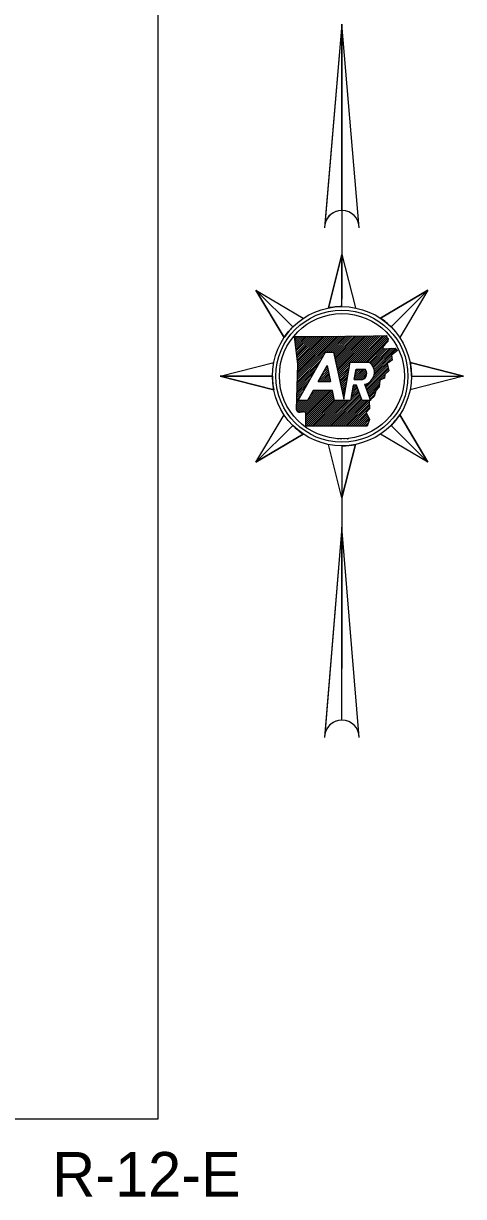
# Model space of a CAD drawing. Extents: x 171 to 3403, y 68 to 2102.
# Drawn here: x 2434 to 2632, y 198 to 725 of the extents above; entities that cross this region are included whole.
import ezdxf

# ---------------------------------------------------------------- set-up
doc = ezdxf.new("R2010")
doc.units = 0
for name, color, linetype in [('Default', 7, 'Continuous'), ('R_Draft', 7, 'Continuous'), ('R_No Plot', 7, 'Continuous')]:
    doc.layers.add(name, color=color, linetype=linetype)

msp = doc.modelspace()

# ---------------------------------------------------------------- linework, layer by layer
at = {"layer": 'R_Draft'}
for p, q in [((2576.92, 724.57), (2569.22, 634.49)), ((2576.92, 724.57), (2576.92, 601.2)), ((2576.92, 640.98), (2576.92, 724.57)), ((2569.33, 635.75), (2569.68, 636.1)), ((2569.37, 636.23), (2570.08, 636.94)), ((2576.92, 621.23), (2570.83, 597.19)), ((2576.92, 597.79), (2576.92, 621.23)), ((2538.25, 605.21), (2554.82, 588.64)), ((2554.82, 588.64), (2538.25, 605.21)), ((2538.25, 605.21), (2550.94, 583.91)), ((2615.59, 605.21), (2594.29, 592.52)), ((2599.01, 588.64), (2615.59, 605.21)), ((2599.01, 588.64), (2615.59, 605.21)), ((2555.62, 584.15), (2555.89, 584.43)), ((2555.71, 583.37), (2556.78, 584.43)), ((2555.81, 582.58), (2557.66, 584.43)), ((2555.91, 581.79), (2558.54, 584.43)), ((2556.01, 581.01), (2559.43, 584.43)), ((2556.11, 580.22), (2560.31, 584.43)), ((2556.2, 579.44), (2561.19, 584.42)), ((2556.3, 578.65), (2562.08, 584.42)), ((2556.4, 577.86), (2562.96, 584.42)), ((2556.5, 577.08), (2563.84, 584.42)), ((2556.6, 576.29), (2564.73, 584.42)), ((2556.69, 575.51), (2565.61, 584.42)), ((2556.79, 574.72), (2566.49, 584.42)), ((2556.89, 573.93), (2567.38, 584.42)), ((2556.92, 565.13), (2576.23, 584.44)), ((2556.95, 566.04), (2575.35, 584.44)), ((2556.98, 566.95), (2574.46, 584.43)), ((2556.99, 573.15), (2568.26, 584.42)), ((2557.01, 567.87), (2573.57, 584.43)), ((2557.04, 568.78), (2572.69, 584.43)), ((2557.07, 569.7), (2571.8, 584.43)), ((2557.08, 572.36), (2569.15, 584.42)), ((2557.1, 570.61), (2570.92, 584.43)), ((2557.13, 571.52), (2570.03, 584.43)), ((2570.04, 577.37), (2577.12, 584.44)), ((2570.93, 577.37), (2578, 584.44)), ((2571.81, 577.37), (2578.89, 584.45)), ((2572.7, 577.37), (2579.79, 584.46)), ((2573.25, 577.03), (2580.69, 584.48)), ((2573.4, 576.31), (2581.59, 584.49)), ((2573.56, 575.58), (2582.49, 584.51)), ((2573.71, 574.85), (2583.38, 584.52)), ((2573.87, 574.12), (2584.28, 584.53)), ((2574.03, 573.39), (2585.18, 584.55)), ((2574.18, 572.67), (2586.08, 584.56)), ((2574.34, 571.94), (2586.98, 584.58)), ((2574.49, 571.21), (2587.87, 584.59)), ((2574.65, 570.48), (2588.77, 584.6)), ((2574.8, 569.75), (2589.67, 584.62)), ((2574.96, 569.02), (2590.57, 584.63)), ((2575.12, 568.3), (2591.47, 584.65)), ((2575.27, 567.57), (2592.37, 584.67)), ((2581.41, 572.82), (2593.28, 584.69)), ((2582.3, 572.82), (2594.18, 584.71)), ((2583.18, 572.82), (2595.09, 584.73)), ((2584.06, 572.82), (2595.99, 584.75)), ((2584.95, 572.82), (2596.9, 584.77)), ((2585.83, 572.82), (2597.09, 584.09)), ((2586.72, 572.82), (2597.52, 583.63)), ((2587.6, 572.82), (2597.63, 582.86)), ((2588.48, 572.82), (2595.62, 579.96)), ((2556.89, 564.21), (2568.82, 576.14)), ((2557.18, 555.59), (2569.51, 577.37)), ((2569.51, 577.37), (2573.18, 577.37)), ((2589.29, 572.74), (2595.44, 578.9)), ((2589.77, 572.34), (2596.37, 578.95)), ((2590.2, 571.89), (2597.31, 579)), ((2590.58, 571.39), (2598.24, 579.04)), ((2590.91, 570.83), (2599.17, 579.09)), ((2591.18, 570.22), (2600.1, 579.14)), ((2591.32, 566.83), (2599.35, 574.85)), ((2591.38, 569.54), (2600.94, 579.1)), ((2591.5, 568.77), (2601.35, 578.62)), ((2591.51, 567.89), (2599.24, 575.63)), ((2600.96, 577.35), (2601.77, 578.15)), ((2556.8, 561.47), (2565.35, 570.02)), ((2556.83, 562.38), (2566.51, 572.06)), ((2556.86, 563.3), (2567.66, 574.1)), ((2566.25, 564.14), (2570.28, 571.26)), ((2567.35, 566.08), (2570.68, 569.41)), ((2568.5, 568.12), (2570.52, 570.14)), ((2569.66, 570.15), (2570.37, 570.87)), ((2575.43, 566.84), (2580.44, 571.86)), ((2575.58, 566.11), (2580.26, 570.79)), ((2575.74, 565.38), (2580.07, 569.72)), ((2580.61, 572.82), (2589.17, 572.82)), ((2582.48, 565.1), (2587.13, 569.75)), ((2582.66, 566.17), (2586.24, 569.75)), ((2582.84, 567.24), (2585.36, 569.75)), ((2583.03, 568.31), (2584.47, 569.75)), ((2583.22, 569.38), (2583.59, 569.75)), ((2583.28, 569.75), (2587.3, 569.75)), ((2583.36, 565.1), (2587.62, 569.36)), ((2587.67, 561.41), (2597.47, 571.21)), ((2587.91, 560.76), (2597.64, 570.49)), ((2588.15, 560.12), (2597.8, 569.77)), ((2588.39, 559.47), (2597.97, 569.05)), ((2590.55, 565.17), (2597.31, 571.93)), ((2598.36, 572.97), (2599.45, 574.07)), ((2631.6, 566.54), (2607.57, 572.62)), ((2522.23, 566.54), (2545.67, 566.54)), ((2545.67, 566.54), (2522.23, 566.54)), ((2522.23, 566.54), (2546.27, 560.45)), ((2556.71, 558.73), (2561.89, 563.91)), ((2556.74, 559.64), (2563.05, 565.95)), ((2556.77, 560.55), (2564.2, 567.99)), ((2566.25, 564.14), (2571.81, 564.14)), ((2566.29, 564.14), (2570.84, 568.68)), ((2567.18, 564.14), (2570.99, 567.95)), ((2568.06, 564.14), (2571.15, 567.22)), ((2568.95, 564.14), (2571.3, 566.5)), ((2569.83, 564.14), (2571.46, 565.77)), ((2570.71, 564.14), (2571.62, 565.04)), ((2571.6, 564.14), (2571.77, 564.31)), ((2575.9, 564.66), (2579.88, 568.64)), ((2576.05, 563.93), (2579.7, 567.57)), ((2576.21, 563.2), (2579.51, 566.5)), ((2576.36, 562.47), (2579.32, 565.43)), ((2576.52, 561.74), (2579.14, 564.36)), ((2582.47, 565.1), (2586.14, 565.1)), ((2584.24, 565.1), (2587.92, 568.77)), ((2585.13, 565.1), (2588.08, 568.05)), ((2586.01, 565.1), (2588.01, 567.1)), ((2588.63, 558.83), (2593.93, 564.13)), ((2594.95, 565.15), (2596.19, 566.39)), ((2608.17, 566.54), (2631.6, 566.54)), ((2608.17, 566.54), (2631.6, 566.54)), ((2556.65, 556.9), (2559.58, 559.84)), ((2556.68, 557.81), (2560.74, 561.87)), ((2556.81, 550.87), (2566.1, 560.16)), ((2557.33, 550.51), (2566.98, 560.16)), ((2557.97, 550.26), (2567.86, 560.16)), ((2559.02, 550.43), (2568.75, 560.16)), ((2559.91, 550.44), (2569.63, 560.16)), ((2560.61, 550.25), (2570.52, 560.16)), ((2560.64, 548.52), (2572.28, 560.16)), ((2560.64, 549.4), (2571.4, 560.16)), ((2560.64, 547.63), (2572.75, 559.74)), ((2560.64, 546.75), (2572.91, 559.01)), ((2564, 560.16), (2561.41, 555.59)), ((2562.41, 557.36), (2565.21, 560.16)), ((2563.57, 559.4), (2564.33, 560.16)), ((2572.66, 560.16), (2564, 560.16)), ((2569.49, 544.11), (2584.69, 559.31)), ((2570.37, 544.1), (2584.93, 558.66)), ((2576.67, 561.02), (2578.95, 563.29)), ((2576.83, 560.29), (2578.76, 562.22)), ((2576.99, 559.56), (2578.58, 561.15)), ((2577.14, 558.83), (2578.39, 560.08)), ((2577.3, 558.1), (2578.2, 559.01)), ((2580.97, 556.47), (2584.45, 559.95)), ((2581.15, 557.54), (2584.21, 560.6)), ((2581.34, 558.61), (2583.97, 561.24)), ((2581.53, 559.68), (2583.74, 561.89)), ((2581.71, 560.75), (2583.48, 562.52)), ((2581.9, 561.82), (2582.6, 562.52)), ((2583.5, 562.52), (2582.02, 562.52)), ((2586.06, 555.59), (2583.5, 562.52)), ((2587.13, 562.89), (2589.82, 555.59)), ((2587.2, 562.7), (2587.47, 562.97)), ((2587.44, 562.05), (2589.12, 563.74)), ((2588.87, 558.18), (2593.83, 563.15)), ((2589.11, 557.54), (2593.73, 562.16)), ((2589.34, 556.89), (2592.05, 559.6)), ((2556.48, 551.43), (2560.64, 555.59)), ((2556.49, 552.33), (2559.76, 555.59)), ((2556.52, 553.24), (2558.88, 555.59)), ((2556.55, 554.15), (2557.99, 555.59)), ((2556.58, 555.07), (2557.28, 555.76)), ((2556.62, 555.98), (2558.43, 557.8)), ((2561.41, 555.59), (2557.18, 555.59)), ((2560.65, 545.87), (2573.06, 558.29)), ((2560.65, 544.99), (2573.22, 557.56)), ((2560.66, 544.12), (2573.37, 556.83)), ((2561.55, 544.12), (2573.53, 556.1)), ((2562.43, 544.12), (2573.9, 555.59)), ((2563.31, 544.12), (2574.79, 555.59)), ((2564.19, 544.11), (2575.67, 555.59)), ((2565.07, 544.11), (2576.55, 555.59)), ((2565.96, 544.11), (2577.44, 555.59)), ((2566.84, 544.11), (2578.32, 555.59)), ((2567.72, 544.11), (2579.21, 555.59)), ((2568.6, 544.11), (2580.09, 555.59)), ((2571.25, 544.1), (2585.17, 558.02)), ((2572.13, 544.1), (2585.4, 557.37)), ((2573.02, 544.1), (2585.64, 556.73)), ((2580.81, 555.59), (2573.64, 555.59)), ((2573.9, 544.1), (2585.88, 556.08)), ((2574.78, 544.1), (2586.28, 555.59)), ((2575.66, 544.1), (2587.16, 555.59)), ((2576.55, 544.09), (2588.04, 555.59)), ((2577.43, 544.09), (2588.93, 555.59)), ((2577.45, 557.38), (2578.02, 557.94)), ((2577.61, 556.65), (2577.83, 556.87)), ((2578.31, 544.09), (2589.22, 555)), ((2579.19, 544.09), (2589.26, 554.16)), ((2580.08, 544.09), (2589.3, 553.32)), ((2589.82, 555.59), (2586.06, 555.59)), ((2589.58, 556.25), (2591.68, 558.34)), ((2580.96, 544.09), (2589.34, 552.47)), ((2581.84, 544.09), (2587.89, 550.14)), ((2582.72, 544.08), (2588.16, 549.52)), ((2583.61, 544.08), (2588.44, 548.91)), ((2584.49, 544.08), (2588.71, 548.3)), ((2615.59, 527.87), (2602.89, 549.17)), ((2538.25, 527.87), (2554.82, 544.44)), ((2554.82, 544.44), (2538.25, 527.87)), ((2585.37, 544.08), (2588.98, 547.69)), ((2586.25, 544.08), (2589.21, 547.04)), ((2587.14, 544.08), (2588.81, 545.75)), ((2588.02, 544.08), (2588.41, 544.47)), ((2599.01, 544.44), (2615.59, 527.87)), ((2599.01, 544.44), (2615.59, 527.87)), ((2538.25, 527.87), (2559.55, 540.56)), ((2576.92, 511.85), (2583, 535.89)), ((2576.92, 535.29), (2576.92, 535.29)), ((2576.92, 535.29), (2576.92, 435.25)), ((2576.92, 535.29), (2576.92, 511.85)), ((2576.92, 498.79), (2569.21, 405.54)), ((2576.92, 412.07), (2576.92, 498.79))]:
    msp.add_line(p, q, dxfattribs=at)
for points in [[(2584.73, 633.16), (2576.92, 724.57), (2569.1, 633.16)], [(2570.83, 597.19), (2576.92, 621.23), (2583, 597.19)], [(2550.94, 583.91), (2538.25, 605.21), (2559.55, 592.52)], [(2594.29, 592.52), (2615.59, 605.21), (2602.89, 583.91)], [(2555.58, 584.43), (2567.78, 584.42), (2578.48, 584.44), (2591.1, 584.64), (2596.95, 584.77)], [(2556.46, 551.44), (2557.14, 571.89), (2555.58, 584.43)], [(2573.18, 577.37), (2577.71, 556.17), (2580.61, 572.82)], [(2600.78, 579.17), (2601.84, 578.07), (2599.21, 575.91), (2599.49, 573.72), (2597.24, 572.24), (2598.01, 568.88), (2596.27, 567.29), (2596.11, 565.57), (2594, 564.81), (2593.67, 561.55), (2592.15, 559.92), (2591.42, 557.47), (2589.2, 555.45), (2589.37, 551.87), (2587.87, 550.19), (2589.24, 547.12), (2588.29, 544.08)], [(2595.14, 578.89), (2600.87, 579.18)], [(2546.27, 560.45), (2522.23, 566.54), (2546.27, 572.62)], [(2570.28, 571.26), (2571.81, 564.14)], [(2582.47, 565.1), (2583.28, 569.75)], [(2607.57, 572.62), (2631.6, 566.54), (2607.57, 560.45)], [(2573.64, 555.59), (2572.66, 560.16)], [(2582.02, 562.52), (2580.81, 555.59)], [(2559.55, 540.56), (2538.25, 527.87), (2550.94, 549.17)], [(2588.29, 544.08), (2560.65, 544.12), (2560.63, 550.22)], [(2602.89, 549.17), (2615.59, 527.87), (2594.29, 540.56)], [(2583, 535.89), (2576.92, 511.85), (2570.83, 535.89)], [(2584.73, 404.26), (2576.92, 498.79), (2569.1, 404.26)]]:
    msp.add_lwpolyline(points, dxfattribs=at)
for radius in [31.25, 29.69, 28.13]:
    msp.add_circle((2576.92, 566.54), radius, dxfattribs=at)
for centre, radius, start, end in [((2576.92, 633.16), 7.81, 0, 180), ((2576.92, 633.16), 7.81, 90, 170.2296), ((2576.92, 566.54), 31.25, 90, 101.2291), ((2576.92, 566.54), 31.25, 45, 56.2291), ((2576.92, 566.54), 31.25, 135, 146.2291), ((2585.26, 567.79), 2.83, 288.1268, 43.8902), ((2585.99, 568.3), 5.53, 281.8626, 54.8705), ((2576.92, 566.54), 31.25, 0, 11.2291), ((2576.92, 566.54), 31.25, 180, 191.2291), ((2576.92, 566.54), 31.25, 315, 326.2291), ((2576.92, 566.54), 31.25, 225, 236.2291), ((2576.92, 566.54), 31.25, 270, 281.2291), ((2576.92, 404.26), 7.81, 0, 180), ((2576.92, 404.26), 7.81, 90, 170.5511)]:
    msp.add_arc(centre, radius, start, end, dxfattribs=at)
for points in [[(2596.95, 584.77), (2596.99, 584.44), (2597.1, 584.27), (2597.11, 583.95), (2597.24, 583.82), (2597.46, 583.68), (2597.65, 583.46), (2597.7, 583.21), (2597.64, 582.94), (2597.62, 582.65), (2597.59, 582.39), (2597.55, 582.16), (2597.37, 581.97), (2597.19, 581.83), (2597.04, 581.68), (2596.92, 581.51), (2596.73, 581.33), (2596.53, 581.14), (2596.37, 580.97), (2596.21, 580.76), (2596.14, 580.53), (2595.97, 580.36), (2595.83, 580.21), (2595.65, 580.01), (2595.56, 579.81), (2595.38, 579.57), (2595.35, 579.35), (2595.23, 579.16), (2595.23, 579.13)], [(2560.63, 550.22), (2560.66, 550.21), (2560.52, 550.3), (2560.33, 550.4), (2560.11, 550.42), (2559.83, 550.45), (2559.59, 550.48), (2559.35, 550.64), (2559.1, 550.47), (2558.81, 550.35), (2558.64, 550.49), (2558.43, 550.39), (2558.27, 550.44), (2558.01, 550.26), (2557.76, 550.33), (2557.58, 550.27), (2557.35, 550.28), (2557.31, 550.54), (2557.09, 550.58), (2556.9, 550.68), (2556.77, 550.95), (2556.68, 551.15), (2556.46, 551.44)]]:
    msp.add_spline(points, degree=3, dxfattribs=at)
at = {"layer": 'R_No Plot'}
msp.add_lwpolyline([(1054.72, 1159.82), (2494.17, 1159.82), (2494.17, 232.79), (1054.72, 232.79)], close=True, dxfattribs=at)

# ---------------------------------------------------------------- texts
at = {"layer": 'Default'}
msp.add_text('R-12-E', height=20, dxfattribs=at).set_placement((2446.67, 198.09))
at = {"layer": 'R_Draft'}
msp.add_text('DWB 7-27-17', height=0.6076, dxfattribs=at).set_placement((2575, 537.89))

doc.saveas('drawing.dxf')
